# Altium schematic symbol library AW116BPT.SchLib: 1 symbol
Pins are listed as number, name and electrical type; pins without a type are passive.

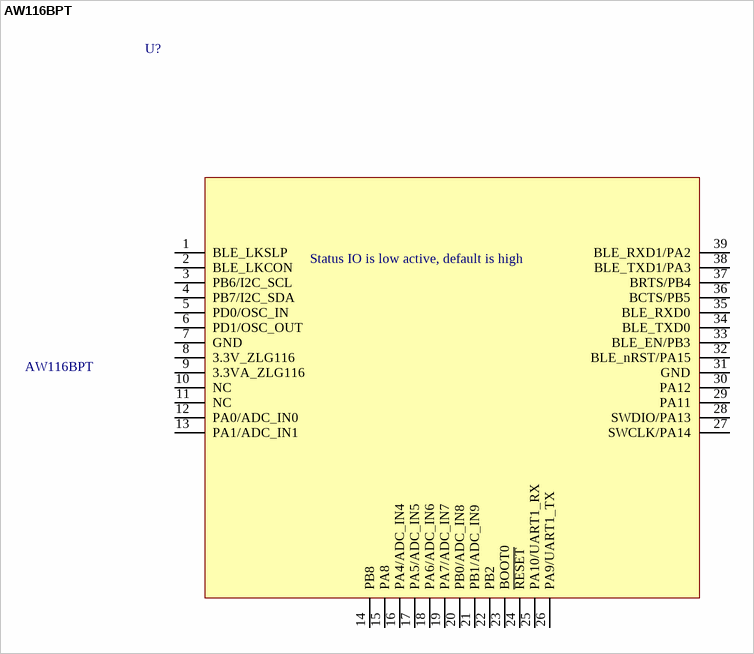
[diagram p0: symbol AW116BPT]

## AW116BPT
designator U?
footprint AW116BPT
footprint AW116BPT
pins: 1 BLE_LKSLP, 2 BLE_LKCON, 3 PB6/I2C_SCL, 4 PB7/I2C_SDA, 5 PD0/OSC_IN, 6 PD1/OSC_OUT, 7 GND, 8 3.3V_ZLG116, 9 3.3VA_ZLG116, 10 NC, 11 NC, 12 PA0/ADC_IN0, 13 PA1/ADC_IN1, 14 PB8, 15 PA8, 16 PA4/ADC_IN4, 17 PA5/ADC_IN5, 18 PA6/ADC_IN6, 19 PA7/ADC_IN7, 20 PB0/ADC_IN8, 21 PB1/ADC_IN9, 22 PB2, 23 BOOT0, 24 ~{RESET}, 25 PA10/UART1_RX, 26 PA9/UART1_TX, 27 SWCLK/PA14, 28 SWDIO/PA13, 29 PA11, 30 PA12, 31 GND, 32 BLE_nRST/PA15, 33 BLE_EN/PB3, 34 BLE_TXD0, 35 BLE_RXD0, 36 BCTS/PB5, 37 BRTS/PB4, 38 BLE_TXD1/PA3, 39 BLE_RXD1/PA2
